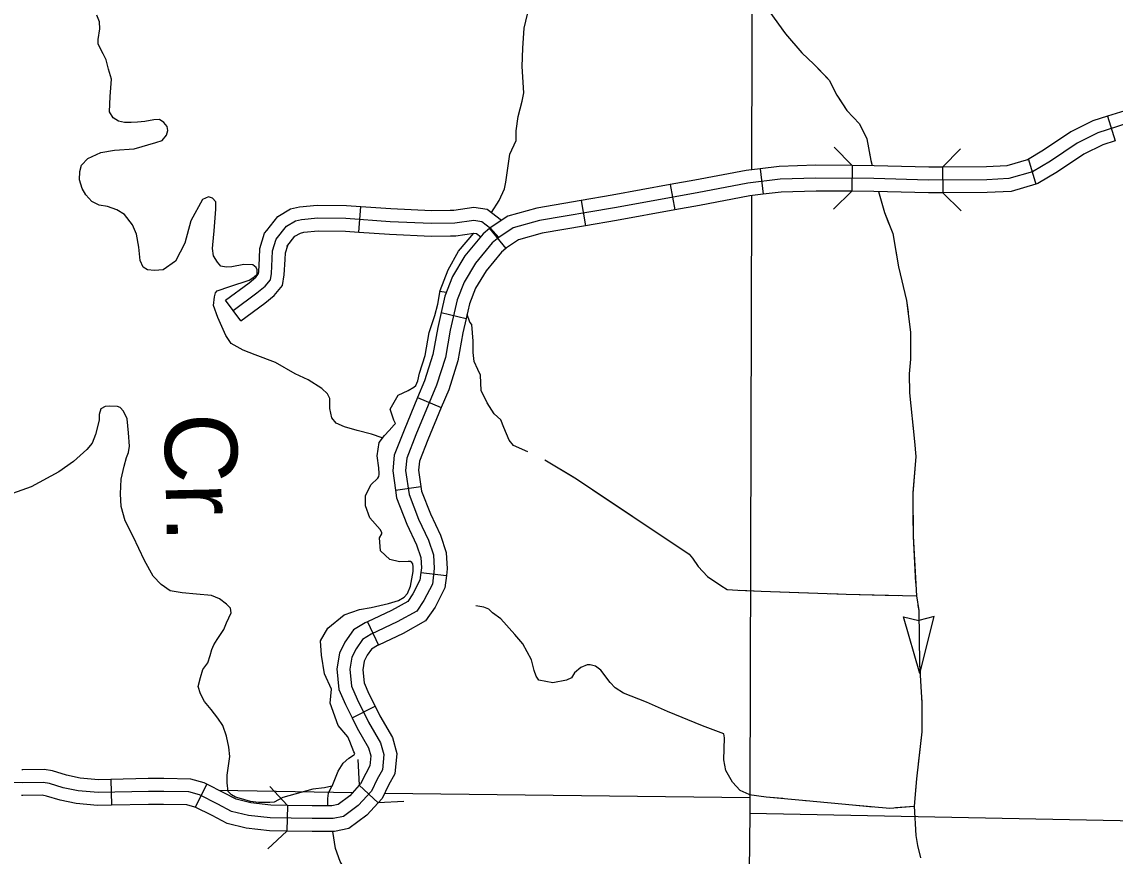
# Model space of a CAD drawing. Extents: x 1369979 to 1371646, y 379997 to 381064.
# Drawn here: x 1370868.8 to 1370943.5, y 380415 to 380472 of the extents above; entities that cross this region are included whole.
import ezdxf

# ---------------------------------------------------------------- set-up
doc = ezdxf.new("R2010")
doc.units = 0
doc.layers.add('R_Border Notes', color=7, linetype='Continuous')

msp = doc.modelspace()

# ---------------------------------------------------------------- linework, layer by layer
at = {"layer": 'R_Border Notes'}
for p, q in [((1370943.014, 380465.57), (1370943.544, 380463.894)), ((1370937.634, 380462.616), (1370938.125, 380460.928)), ((1370919.293, 380461.986), (1370919.5, 380460.24)), ((1370925.58, 380462.203), (1370925.557, 380460.446)), ((1370931.754, 380462.096), (1370931.767, 380460.338)), ((1370913.145, 380460.902), (1370913.464, 380459.174)), ((1370891.873, 380457.657), (1370891.994, 380459.41)), ((1370907.068, 380459.815), (1370907.36, 380458.081)), ((1370900.803, 380457.901), (1370901.921, 380456.544)), ((1370883.815, 380451.6), (1370882.767, 380453.011)), ((1370897.488, 380452.153), (1370899.202, 380451.762)), ((1370895.879, 380446.353), (1370897.503, 380445.679)), ((1370894.371, 380440.023), (1370896.111, 380440.271)), ((1370896.103, 380434.404), (1370897.848, 380434.192)), ((1370892.459, 380431.037), (1370893.208, 380429.447)), ((1370930.193, 380427.503), (1370929.09, 380431.371)), ((1370929.09, 380431.371), (1370930.128, 380431.111)), ((1370931.171, 380431.405), (1370930.142, 380431.111)), ((1370930.193, 380427.503), (1370931.171, 380431.405)), ((1370891.404, 380424.481), (1370892.976, 380425.267)), ((1370874.922, 380420.258), (1370874.962, 380418.5)), ((1370881.48, 380419.937), (1370880.694, 380418.365)), ((1370891.901, 380419.867), (1370893.193, 380418.674)), ((1370886.988, 380418.493), (1370886.956, 380416.735))]:
    msp.add_line(p, q, dxfattribs=at)
for points in [[(1370920.37, 380581.601), (1370919.796, 380543.55), (1370919.771, 380541.901), (1370918.746, 380480.774), (1370918.743, 380479.316), (1370918.699, 380461.915)], [(1370911.675, 380481.736), (1370913.213, 380480.049), (1370914.247, 380478.747), (1370915.223, 380477.534), (1370916.228, 380476.41), (1370916.819, 380475.699), (1370917.795, 380474.545), (1370918.711, 380473.806), (1370919.953, 380472.681), (1370921.017, 380471.202), (1370922.141, 380469.9), (1370922.968, 380469.13), (1370924.003, 380468.036), (1370924.535, 380467), (1370925.215, 380465.964), (1370926.072, 380465.047), (1370926.576, 380464.018)], [(1370903.019, 380466.604), (1370903.14, 380467.175), (1370903.034, 380468.965), (1370903.065, 380470.224), (1370903.171, 380471.589), (1370903.398, 380472.545), (1370903.807, 380474.866)], [(1370874.881, 380466.924), (1370874.968, 380468.095), (1370874.752, 380468.787), (1370874.593, 380469.421), (1370874.392, 380469.825), (1370874.061, 380470.487), (1370874.061, 380470.804), (1370874.176, 380471.554), (1370874.147, 380472.015), (1370873.96, 380472.487)], [(1370920.767, 380471.55), (1370921.017, 380471.202), (1370922.141, 380469.9), (1370922.968, 380469.13), (1370923.904, 380468.141)], [(1370960.78, 380468.907), (1370958.953, 380468.254), (1370957.806, 380467.758), (1370955.98, 380467.419), (1370954.284, 380467.366), (1370952.458, 380467.654), (1370950.684, 380467.941), (1370949.51, 380467.706), (1370948.388, 380467.21), (1370946.719, 380466.009), (1370945.31, 380465.277), (1370944.423, 380465.095), (1370942.362, 380464.442), (1370940.953, 380463.737), (1370939.127, 380462.509), (1370937.901, 380461.778), (1370936.284, 380461.308), (1370934.787, 380461.236)], [(1370948.433, 380468.191), (1370947.949, 380467.977), (1370946.257, 380466.759), (1370945.013, 380466.114), (1370944.201, 380465.946), (1370943.014, 380465.57)], [(1370875.846, 380458.86), (1370875.342, 380459.171), (1370874.694, 380459.416), (1370874.118, 380459.503), (1370873.629, 380459.748), (1370873.211, 380460.209), (1370872.967, 380460.641), (1370872.779, 380461.232), (1370872.808, 380461.794), (1370872.923, 380462.226), (1370873.341, 380462.673), (1370874.233, 380463.091), (1370875.169, 380463.249), (1370876.508, 380463.35), (1370877.991, 380463.783), (1370878.437, 380463.912), (1370878.725, 380464.287), (1370878.811, 380464.604), (1370878.768, 380464.863), (1370878.538, 380465.151), (1370878.236, 380465.353), (1370877.861, 380465.324), (1370877.242, 380465.209), (1370876.753, 380465.166), (1370876.306, 380465.151), (1370875.846, 380465.151), (1370875.443, 380465.238), (1370875.083, 380465.454), (1370874.838, 380465.872), (1370874.881, 380466.924)], [(1370924.666, 380466.801), (1370925.215, 380465.964), (1370926.072, 380465.047), (1370926.576, 380464.018), (1370926.804, 380462.801)], [(1370902.195, 380462.984), (1370902.625, 380463.904), (1370902.625, 380464.571), (1370902.762, 380465.557), (1370903.019, 380466.604)], [(1370943.014, 380465.57), (1370942.031, 380465.259), (1370940.51, 380464.498), (1370938.657, 380463.252), (1370937.548, 380462.591), (1370937.634, 380462.616)], [(1370926.576, 380464.018), (1370926.853, 380462.542), (1370926.933, 380462.197)], [(1370943.544, 380463.894), (1370942.693, 380463.625), (1370941.397, 380462.976), (1370939.598, 380461.767), (1370938.254, 380460.966), (1370938.124, 380460.928)], [(1370924.353, 380463.462), (1370925.58, 380462.203)], [(1370931.754, 380462.096), (1370932.988, 380463.348)], [(1370900.93, 380458.992), (1370901.458, 380459.804), (1370901.828, 380460.622), (1370901.918, 380461.069), (1370902.195, 380462.984)], [(1370937.634, 380462.616), (1370936.138, 380462.181), (1370934.763, 380462.115), (1370931.754, 380462.096)], [(1370919.293, 380461.986), (1370918.323, 380461.87), (1370914.825, 380461.212), (1370913.145, 380460.902)], [(1370925.58, 380462.203), (1370923.088, 380462.22), (1370920.581, 380462.139), (1370919.292, 380461.986)], [(1370931.754, 380462.096), (1370930.805, 380462.089), (1370927.08, 380462.193), (1370925.58, 380462.203)], [(1370934.787, 380461.236), (1370930.795, 380461.21), (1370927.065, 380461.314), (1370923.1, 380461.341), (1370920.647, 380461.262), (1370918.456, 380461.001), (1370914.986, 380460.348), (1370909.326, 380459.304), (1370904.212, 380458.442), (1370902.412, 380457.946), (1370901.432, 380457.28), (1370900.988, 380456.914), (1370899.84, 380455.53), (1370899.058, 380454.225), (1370898.588, 380453.024), (1370898.119, 380450.961), (1370897.779, 380449.081), (1370897.179, 380447.193), (1370895.771, 380443.798), (1370895.145, 380442.205), (1370895.066, 380441.369), (1370895.301, 380439.724), (1370895.953, 380438.053), (1370896.632, 380436.617), (1370896.971, 380435.598), (1370897.023, 380434.684), (1370896.892, 380433.614), (1370896.319, 380432.491), (1370895.823, 380431.76), (1370894.492, 380431.023)], [(1370913.145, 380460.902), (1370909.173, 380460.169), (1370907.068, 380459.815)], [(1370938.125, 380460.928), (1370936.43, 380460.435), (1370934.811, 380460.357), (1370931.767, 380460.338)], [(1370881.893, 380456.79), (1370881.984, 380457.753), (1370882.105, 380459.224), (1370882.09, 380459.725), (1370881.862, 380459.983), (1370881.589, 380460.059), (1370881.195, 380459.892), (1370880.377, 380458.436), (1370879.968, 380456.903), (1370879.346, 380455.659), (1370878.498, 380455.083), (1370877.907, 380455.037), (1370877.437, 380455.083), (1370877.134, 380455.265), (1370876.922, 380455.705), (1370876.831, 380456.63), (1370876.679, 380457.525), (1370876.391, 380458.147), (1370875.846, 380458.86)], [(1370919.5, 380460.24), (1370918.589, 380460.132), (1370915.147, 380459.484), (1370913.464, 380459.174)], [(1370918.694, 380460.144), (1370918.59, 380419.032), (1370918.577, 380417.955), (1370917.873, 380356.557), (1370917.867, 380355.995), (1370917.282, 380325.614), (1370917.407, 380294.406), (1370917.409, 380293.913), (1370917.399, 380293.195)], [(1370925.557, 380460.446), (1370923.111, 380460.462), (1370920.714, 380460.385), (1370919.5, 380460.24)], [(1370925.557, 380460.446), (1370924.297, 380459.219)], [(1370931.767, 380460.338), (1370930.786, 380460.331), (1370927.05, 380460.436), (1370925.557, 380460.446)], [(1370927.371, 380460.427), (1370927.788, 380458.987), (1370928.35, 380457.567), (1370928.734, 380455.289), (1370929.296, 380452.98), (1370929.562, 380450.82), (1370929.562, 380448.977), (1370929.473, 380447.971), (1370929.503, 380446.669), (1370929.828, 380443.355), (1370929.917, 380442.319), (1370929.71, 380439.804), (1370929.739, 380436.875), (1370929.962, 380432.8), (1370930.124, 380431.806), (1370930.183, 380428.137), (1370930.331, 380425.474), (1370930.331, 380423.521), (1370929.976, 380420.313), (1370929.806, 380418.428), (1370929.917, 380416.437), (1370930.035, 380415.756), (1370930.242, 380414.898)], [(1370927.371, 380460.427), (1370927.788, 380458.987), (1370928.09, 380458.223)], [(1370933.019, 380459.104), (1370931.767, 380460.338)], [(1370885.575, 380457.773), (1370886.331, 380458.726), (1370887.208, 380459.238), (1370887.811, 380459.389), (1370889.02, 380459.504), (1370891.023, 380459.477), (1370891.994, 380459.41)], [(1370891.994, 380459.41), (1370894.063, 380459.267), (1370896.843, 380459.138), (1370898.098, 380459.159)], [(1370898.098, 380459.159), (1370898.353, 380459.163), (1370899.727, 380459.356), (1370900.63, 380459.227), (1370901.607, 380458.461)], [(1370907.068, 380459.815), (1370904.022, 380459.301), (1370902.039, 380458.755), (1370900.904, 380457.984), (1370900.803, 380457.901)], [(1370883.291, 380452.305), (1370884.908, 380453.507), (1370885.456, 380453.951), (1370885.821, 380454.395), (1370885.899, 380454.838), (1370885.952, 380455.831), (1370885.978, 380456.379), (1370886.212, 380457.163), (1370886.917, 380458.05), (1370887.543, 380458.416), (1370887.96, 380458.52), (1370889.056, 380458.625), (1370890.986, 380458.599), (1370894.012, 380458.39), (1370896.83, 380458.259), (1370898.421, 380458.285), (1370899.726, 380458.468), (1370900.273, 380458.39), (1370900.873, 380457.92), (1370901.432, 380457.28)], [(1370913.464, 380459.174), (1370909.478, 380458.438), (1370907.36, 380458.081)], [(1370882.767, 380453.011), (1370884.369, 380454.201), (1370884.834, 380454.578), (1370884.996, 380454.775), (1370885.024, 380454.938), (1370885.074, 380455.875), (1370885.105, 380456.528), (1370885.419, 380457.576), (1370885.575, 380457.773)], [(1370900.803, 380457.901), (1370900.365, 380457.54), (1370899.121, 380456.04), (1370898.266, 380454.613), (1370897.746, 380453.283), (1370897.488, 380452.153)], [(1370907.36, 380458.081), (1370904.403, 380457.583), (1370902.786, 380457.137), (1370901.959, 380456.576), (1370901.921, 380456.544)], [(1370886.952, 380456.68), (1370887.503, 380457.375), (1370887.878, 380457.594), (1370888.109, 380457.652), (1370889.092, 380457.745), (1370890.95, 380457.72), (1370891.873, 380457.657)], [(1370891.873, 380457.657), (1370893.962, 380457.512), (1370896.817, 380457.38), (1370898.127, 380457.402)], [(1370897.422, 380453.671), (1370897.963, 380455.067), (1370898.686, 380456.363), (1370899.715, 380457.582)], [(1370898.127, 380457.402), (1370898.49, 380457.407), (1370899.724, 380457.58), (1370899.916, 380457.553), (1370900.195, 380457.335)], [(1370883.966, 380449.59), (1370883.15, 380450.039), (1370882.787, 380450.585), (1370882.241, 380451.814), (1370881.938, 380452.648), (1370881.999, 380453.225), (1370882.074, 380453.498), (1370882.181, 380453.634), (1370883.044, 380453.938), (1370884.378, 380454.362), (1370884.681, 380454.575), (1370884.909, 380454.772), (1370884.909, 380455.075), (1370884.848, 380455.242), (1370884.621, 380455.409), (1370883.999, 380455.439), (1370883.196, 380455.273), (1370882.802, 380455.257), (1370882.438, 380455.318), (1370882.211, 380455.591), (1370881.938, 380456.031), (1370881.877, 380456.532), (1370881.893, 380456.79)], [(1370883.815, 380451.6), (1370885.447, 380452.812), (1370886.078, 380453.324), (1370886.647, 380454.014), (1370886.774, 380454.739), (1370886.829, 380455.787), (1370886.85, 380456.23), (1370887.006, 380456.749), (1370886.952, 380456.68)], [(1370901.921, 380456.544), (1370901.611, 380456.289), (1370900.56, 380455.021), (1370899.849, 380453.836), (1370899.431, 380452.765), (1370899.202, 380451.762)], [(1370928.49, 380456.738), (1370928.734, 380455.289), (1370929.296, 380452.98), (1370929.393, 380452.191)], [(1370893.233, 380441.558), (1370893.127, 380442.374), (1370893.25, 380443.282), (1370893.617, 380443.762), (1370893.941, 380444.103), (1370894.282, 380444.49), (1370894.361, 380444.569), (1370894.252, 380444.803), (1370894.019, 380445.569), (1370894.549, 380446.517), (1370895.228, 380446.845), (1370895.635, 380447.054), (1370895.752, 380447.166), (1370895.902, 380447.501), (1370896.013, 380448.016), (1370896.402, 380449.221), (1370896.675, 380450.805), (1370897.067, 380451.965), (1370897.275, 380452.743), (1370897.422, 380453.671)], [(1370897.839, 380453.521), (1370897.411, 380453.6)], [(1370897.488, 380452.153), (1370897.257, 380451.136), (1370896.925, 380449.293), (1370896.353, 380447.495), (1370895.879, 380446.353)], [(1370903.41, 380442.64), (1370902.443, 380443.072), (1370902.14, 380443.436), (1370901.776, 380444.316), (1370901.579, 380444.832), (1370901.11, 380445.241), (1370900.625, 380446), (1370900.231, 380446.834), (1370900.2, 380447.365), (1370900.185, 380447.881), (1370899.988, 380448.26), (1370899.746, 380448.806), (1370899.685, 380449.428), (1370899.67, 380450.202), (1370899.594, 380451.34), (1370899.458, 380451.499), (1370899.263, 380452.027)], [(1370899.202, 380451.762), (1370898.98, 380450.785), (1370898.634, 380448.869), (1370898.006, 380446.89), (1370897.503, 380445.679)], [(1370929.562, 380450.654), (1370929.562, 380448.977), (1370929.473, 380447.971), (1370929.503, 380446.669), (1370929.567, 380446.021)], [(1370887.512, 380447.967), (1370886.179, 380448.755), (1370884.784, 380449.271), (1370883.966, 380449.59)], [(1370893.462, 380443.6), (1370892.741, 380443.84), (1370891.756, 380444.098), (1370890.877, 380444.356), (1370890.316, 380444.599), (1370890.013, 380444.963), (1370889.892, 380445.6), (1370889.892, 380446.283), (1370889.725, 380446.616), (1370889.331, 380446.981), (1370888.406, 380447.557), (1370887.512, 380447.967)], [(1370895.879, 380446.353), (1370894.956, 380444.127), (1370894.281, 380442.411), (1370894.182, 380441.348), (1370894.371, 380440.023)], [(1370876.193, 380443.02), (1370876.121, 380443.935), (1370876.034, 380444.901), (1370875.789, 380445.419), (1370875.559, 380445.664), (1370875.372, 380445.751), (1370874.839, 380445.765), (1370874.537, 380445.751), (1370874.249, 380445.578), (1370874.134, 380445.203), (1370874.119, 380444.814), (1370873.875, 380443.82), (1370873.644, 380443.229), (1370873.285, 380442.811), (1370872.363, 380441.99), (1370871.37, 380441.27), (1370869.47, 380440.261)], [(1370897.503, 380445.679), (1370896.586, 380443.469), (1370896.008, 380441.999), (1370895.951, 380441.391), (1370896.111, 380440.271)], [(1370929.718, 380444.481), (1370929.828, 380443.355), (1370929.917, 380442.319), (1370929.714, 380439.858)], [(1370877.225, 380435.218), (1370876.437, 380436.853), (1370875.905, 380437.934), (1370875.617, 380438.899), (1370875.574, 380439.778), (1370875.631, 380440.787), (1370875.833, 380441.666), (1370875.991, 380442.257), (1370876.121, 380442.602), (1370876.193, 380443.02)], [(1370904.577, 380442.1), (1370906.744, 380440.795), (1370914.443, 380435.652), (1370914.671, 380435.379), (1370915.05, 380434.803), (1370915.701, 380434.12), (1370916.611, 380433.513), (1370917.035, 380433.24), (1370917.762, 380433.195), (1370919.369, 380433.119), (1370925.173, 380432.922), (1370929.962, 380432.8)], [(1370904.577, 380442.1), (1370906.565, 380440.903)], [(1370895.397, 380433.461), (1370895.587, 380434.458), (1370895.576, 380434.79), (1370895.557, 380435), (1370895.483, 380435.092), (1370895.402, 380435.149), (1370895.24, 380435.149), (1370894.656, 380435.13), (1370893.983, 380435.284), (1370893.338, 380435.883), (1370893.288, 380436.775), (1370893.447, 380437.045), (1370893.445, 380437.135), (1370893.318, 380437.341), (1370892.627, 380438.131), (1370892.317, 380438.945), (1370892.317, 380439.648), (1370892.689, 380440.393), (1370893.166, 380440.855), (1370893.225, 380440.955), (1370893.252, 380441.097), (1370893.227, 380441.629)], [(1370869.47, 380440.261), (1370867.892, 380439.69)], [(1370894.371, 380440.023), (1370894.445, 380439.499), (1370895.146, 380437.705), (1370895.814, 380436.289), (1370896.1, 380435.432), (1370896.141, 380434.713), (1370896.103, 380434.404)], [(1370896.111, 380440.271), (1370896.157, 380439.949), (1370896.761, 380438.401), (1370897.449, 380436.944), (1370897.842, 380435.765), (1370897.905, 380434.656), (1370897.848, 380434.192)], [(1370907.857, 380440.052), (1370911.716, 380437.474)], [(1370929.725, 380438.312), (1370929.739, 380436.875), (1370929.914, 380433.676)], [(1370913.002, 380436.615), (1370914.443, 380435.652), (1370914.671, 380435.379), (1370915.05, 380434.803), (1370915.701, 380434.12), (1370916.465, 380433.61)], [(1370881.044, 380426.112), (1370880.892, 380426.601), (1370881.044, 380427.238), (1370881.211, 380427.769), (1370881.544, 380428.224), (1370881.711, 380428.74), (1370881.817, 380429.149), (1370881.953, 380429.468), (1370882.196, 380429.832), (1370882.635, 380430.5), (1370882.832, 380430.97), (1370883.135, 380431.653), (1370883.09, 380431.956), (1370882.832, 380432.244), (1370882.347, 380432.608), (1370881.802, 380432.836), (1370880.786, 380432.927), (1370879.801, 380433.003), (1370878.983, 380433.154), (1370878.361, 380433.579), (1370877.816, 380434.14), (1370877.225, 380435.218)], [(1370896.103, 380434.404), (1370896.039, 380433.875), (1370895.561, 380432.939), (1370895.213, 380432.427), (1370894.092, 380431.806), (1370892.459, 380431.037)], [(1370897.848, 380434.191), (1370897.746, 380433.353), (1370897.076, 380432.043), (1370896.432, 380431.093), (1370894.893, 380430.24), (1370893.208, 380429.447)], [(1370889.995, 380426.434), (1370889.53, 380427.469), (1370889.324, 380428.746), (1370889.258, 380429.731), (1370889.739, 380430.588), (1370890.854, 380431.508), (1370891.916, 380431.868), (1370892.701, 380432.013), (1370893.894, 380432.289), (1370894.571, 380432.498), (1370894.975, 380432.715), (1370895.186, 380432.957), (1370895.397, 380433.461)], [(1370917.901, 380433.188), (1370919.369, 380433.119), (1370922.538, 380433.011)], [(1370924.084, 380432.959), (1370925.173, 380432.922), (1370928.723, 380432.832)], [(1370902.515, 380430.159), (1370901.567, 380431.232), (1370901.007, 380431.656), (1370900.749, 380431.899), (1370900.416, 380432.036), (1370899.855, 380432.112)], [(1370930.07, 380432.139), (1370930.124, 380431.806), (1370930.183, 380428.137), (1370930.218, 380427.504)], [(1370894.492, 380431.023), (1370892.718, 380430.188), (1370892.118, 380429.822), (1370891.675, 380429.195), (1370891.388, 380428.621), (1370891.258, 380427.785), (1370891.362, 380426.636), (1370891.753, 380425.749), (1370892.536, 380424.182), (1370893.345, 380422.772), (1370893.579, 380421.962), (1370893.475, 380420.918), (1370893.115, 380420.273), (1370892.724, 380419.463), (1370891.832, 380418.489), (1370890.819, 380417.74), (1370890.115, 380417.583), (1370888.68, 380417.583), (1370885.811, 380417.635), (1370884.324, 380417.792), (1370883.176, 380418.079), (1370882.237, 380418.575), (1370880.985, 380419.202), (1370880.254, 380419.411), (1370878.532, 380419.437), (1370877.489, 380419.437), (1370874.045, 380419.359), (1370872.689, 380419.489), (1370871.671, 380419.698), (1370870.732, 380419.985), (1370870.289, 380420.064), (1370868.906, 380420.038), (1370866.637, 380420.064)], [(1370892.459, 380431.037), (1370892.301, 380430.963), (1370891.506, 380430.478), (1370890.919, 380429.648), (1370890.541, 380428.891), (1370890.373, 380427.814), (1370890.5, 380426.414), (1370890.958, 380425.375), (1370891.404, 380424.481)], [(1370912.969, 380424.906), (1370911.532, 380425.532), (1370909.941, 380426.154), (1370909.38, 380426.518), (1370909.047, 380426.882), (1370908.41, 380427.717), (1370908.031, 380428.005), (1370907.667, 380428.096), (1370907.47, 380428.081), (1370907.031, 380427.899), (1370906.607, 380427.535), (1370906.409, 380427.201), (1370906.046, 380427.034), (1370905.121, 380426.852), (1370904.166, 380427.034), (1370903.985, 380427.307), (1370903.848, 380427.702), (1370903.666, 380428.445), (1370903.075, 380429.537), (1370902.515, 380430.159)], [(1370893.208, 380429.447), (1370893.136, 380429.413), (1370892.731, 380429.166), (1370892.431, 380428.743), (1370892.235, 380428.35), (1370892.143, 380427.757), (1370892.224, 380426.859), (1370892.549, 380426.122), (1370892.976, 380425.267)], [(1370890.036, 380419.81), (1370890.447, 380420.837), (1370890.791, 380421.385), (1370891.179, 380421.711), (1370891.507, 380421.911), (1370891.556, 380421.951), (1370891.603, 380422.026), (1370891.519, 380422.145), (1370891.245, 380422.851), (1370891.104, 380423.177), (1370890.464, 380423.957), (1370889.904, 380425.466), (1370889.995, 380426.434)], [(1370890.028, 380419.802), (1370889.516, 380419.68), (1370888.713, 380419.589), (1370887.5, 380419.255), (1370886.667, 380419.028), (1370886.091, 380418.709), (1370885.782, 380418.676), (1370885.332, 380418.694), (1370885.015, 380418.694), (1370884.468, 380418.765), (1370883.85, 380418.932), (1370883.445, 380419.047), (1370883.171, 380419.206), (1370882.938, 380419.437), (1370882.878, 380420.029), (1370882.863, 380420.56), (1370883.06, 380421.819), (1370882.984, 380422.472), (1370882.817, 380423.215), (1370882.575, 380423.958), (1370882.226, 380424.444), (1370881.787, 380425.05), (1370881.317, 380425.581), (1370881.044, 380426.112)], [(1370930.304, 380425.96), (1370930.331, 380425.474), (1370930.331, 380423.64)], [(1370892.976, 380425.267), (1370893.311, 380424.597), (1370894.159, 380423.118), (1370894.471, 380422.044), (1370894.331, 380420.649), (1370893.895, 380419.867), (1370893.459, 380418.965), (1370893.193, 380418.674)], [(1370918.531, 380419.232), (1370917.925, 380419.505), (1370917.394, 380420.066), (1370916.939, 380420.87), (1370916.818, 380421.599), (1370916.848, 380423.116), (1370916.818, 380423.389), (1370915.348, 380423.935), (1370912.969, 380424.906)], [(1370891.404, 380424.481), (1370891.761, 380423.766), (1370892.53, 380422.426), (1370892.688, 380421.88), (1370892.619, 380421.187), (1370892.335, 380420.678), (1370891.989, 380419.962), (1370891.901, 380419.867)], [(1370930.331, 380423.64), (1370930.331, 380423.521), (1370930.089, 380421.333)], [(1370891.902, 380419.866), (1370891.831, 380421.623)], [(1370874.922, 380420.258), (1370874.078, 380420.239), (1370872.82, 380420.36), (1370871.889, 380420.551), (1370870.938, 380420.842), (1370870.358, 380420.944), (1370868.903, 380420.917), (1370868.842, 380420.917)], [(1370881.48, 380419.937), (1370881.305, 380420.025), (1370880.384, 380420.288), (1370878.539, 380420.316), (1370877.479, 380420.316), (1370874.922, 380420.258)], [(1370886.988, 380418.493), (1370885.865, 380418.513), (1370884.477, 380418.659), (1370883.492, 380418.906), (1370882.639, 380419.357), (1370881.48, 380419.937)], [(1370885.782, 380419.771), (1370886.988, 380418.493)], [(1370891.901, 380419.867), (1370891.241, 380419.145), (1370890.446, 380418.557), (1370890.018, 380418.462), (1370888.688, 380418.462), (1370886.988, 380418.493)], [(1370889.753, 380418.462), (1370889.74, 380418.952), (1370889.801, 380419.316), (1370890.028, 380419.802)], [(1370929.929, 380419.795), (1370929.806, 380418.428), (1370929.917, 380416.437), (1370930.035, 380415.756), (1370930.172, 380415.189)], [(1370874.962, 380418.5), (1370874.013, 380418.479), (1370872.558, 380418.619), (1370871.454, 380418.846), (1370870.527, 380419.129), (1370870.22, 380419.183), (1370868.909, 380419.159), (1370868.822, 380419.16)], [(1370882.299, 380419.527), (1370891.44, 380419.363)], [(1370893.637, 380419.332), (1370918.59, 380419.032)], [(1370918.531, 380419.232), (1370919.698, 380419.08), (1370922.441, 380418.822), (1370925.593, 380418.519), (1370928.139, 380418.307), (1370929.806, 380418.428)], [(1370918.531, 380419.232), (1370919.698, 380419.08), (1370920.836, 380418.973)], [(1370880.694, 380418.365), (1370880.664, 380418.379), (1370880.124, 380418.534), (1370878.526, 380418.558), (1370877.499, 380418.558), (1370874.962, 380418.5)], [(1370886.956, 380416.735), (1370885.756, 380416.757), (1370884.17, 380416.924), (1370882.859, 380417.252), (1370881.835, 380417.794), (1370880.694, 380418.365)], [(1370893.193, 380418.674), (1370892.423, 380417.833), (1370891.192, 380416.922), (1370890.212, 380416.704), (1370888.672, 380416.704), (1370886.956, 380416.735)], [(1370894.95, 380418.745), (1370893.193, 380418.674)], [(1370922.376, 380418.829), (1370922.441, 380418.822), (1370925.593, 380418.519), (1370926.997, 380418.402)], [(1370928.539, 380418.336), (1370929.806, 380418.428)], [(1370918.577, 380417.955), (1370951.917, 380417.3)], [(1370886.937, 380416.735), (1370885.658, 380415.529)], [(1370891.98, 380409.419), (1370892.059, 380410.575), (1370892.104, 380411.076), (1370892.089, 380411.485), (1370891.892, 380412.411), (1370891.574, 380413.002), (1370891.059, 380413.852), (1370890.589, 380414.656), (1370890.27, 380415.536), (1370890.093, 380416.704)]]:
    msp.add_lwpolyline(points, dxfattribs=at)

# ---------------------------------------------------------------- texts
msp.add_text('Cr.', height=4.95, rotation=271.21774, dxfattribs=at).set_placement((1370878.564, 380445.246))

doc.saveas('drawing.dxf')
